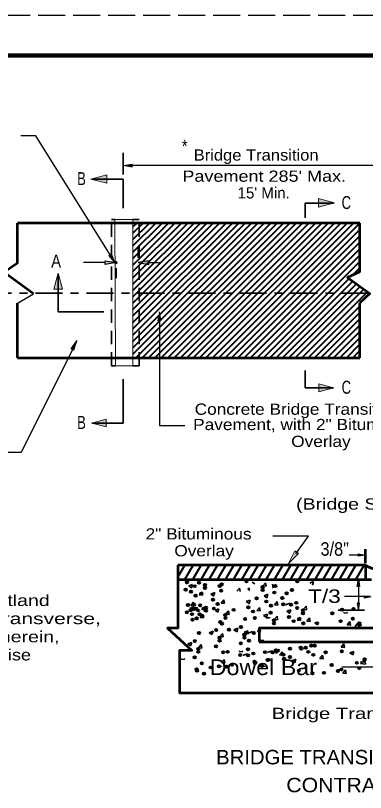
# Model space of a CAD drawing. Extents: x 36.4 to 71.7, y 0.5 to 22.5.
# Drawn here: x 50.93 to 55.29, y 12.78 to 22.48 of the extents above; entities that cross this region are included whole.
import ezdxf

# ---------------------------------------------------------------- set-up
doc = ezdxf.new("R2010")
doc.units = 0
doc.header["$LTSCALE"] = 0.056
doc.header["$PDMODE"] = 32
doc.header["$PDSIZE"] = 0.028
for name, pattern in [('LONG_DASH_SHORT_DASH', [9.9, 6, -1.2, 1.5, -1.2]), ('LONG_DASHED', [7.5, 6, -1.5]), ('MEDIUM_DASHED', [4.5, 3, -1.5])]:
    doc.linetypes.add(name, pattern=pattern)
for name, color, linetype, lineweight in [('1', 7, 'Continuous', 40), ('2', 7, 'MEDIUM_DASHED', 35), ('3', 7, 'Continuous', 13), ('5', 7, 'Continuous', 35), ('6', 7, 'Continuous', 13), ('7', 7, 'LONG_DASH_SHORT_DASH', 35)]:
    doc.layers.add(name, color=color, linetype=linetype, lineweight=lineweight)

msp = doc.modelspace()

# ---------------------------------------------------------------- hatches: boundary and pattern name
at = {"layer": '1'}
for points in [[(52.3805, 20.58408), (52.3805, 20.62158), (52.268, 20.60283), (52.268, 20.60283)], [(52.0445, 19.3695), (52.0445, 19.41475), (52.18058, 19.39217), (52.18058, 19.39217)], [(52.589, 19.3695), (52.589, 19.41475), (52.45283, 19.39217), (52.45283, 19.39217)], [(55.2145, 15.34717), (55.18525, 15.34717), (55.19983, 15.435), (55.19983, 15.435)], [(55.2145, 15.13917), (55.18525, 15.13917), (55.19983, 15.05125), (55.19983, 15.05125)]]:
    msp.add_hatch(color=256, dxfattribs=at).paths.add_polyline_path(points)
at = {"layer": '3'}
for points in [[(52.06208, 20.3825), (52.06208, 20.48933), (51.86283, 20.43583), (51.86283, 20.43583)], [(54.701, 20.19242), (54.701, 20.08558), (54.90033, 20.13908), (54.90033, 20.13908)], [(52.12417, 19.50175), (52.08858, 19.48083), (52.16908, 19.38467), (52.16908, 19.38467)], [(51.40508, 19.06058), (51.51192, 19.06058), (51.45842, 19.25992), (51.45842, 19.25992)], [(52.70158, 18.66583), (52.73908, 18.66583), (52.72025, 18.77833), (52.72025, 18.77833)], [(51.617, 18.31608), (51.65392, 18.29783), (51.69025, 18.41792), (51.69025, 18.41792)], [(54.70775, 17.87742), (54.70775, 17.78025), (54.88892, 17.82892), (54.88892, 17.82892)], [(52.05708, 17.34083), (52.05708, 17.438), (51.87592, 17.38933), (51.87592, 17.38933)], [(54.45417, 15.75925), (54.40658, 15.79342), (54.32783, 15.63367), (54.32783, 15.63367)], [(55.19842, 15.72658), (55.19842, 15.75592), (55.28633, 15.74125), (55.28633, 15.74125)], [(55.27283, 15.23242), (55.27283, 15.20317), (55.36075, 15.21775), (55.36075, 15.21775)]]:
    msp.add_hatch(color=256, dxfattribs=at).paths.add_polyline_path(points)

# ---------------------------------------------------------------- linework, layer by layer
at = {"layer": '1', "linetype": 'LONG_DASHED', "lineweight": 25}
msp.add_line((71.60142, 22.47742), (36.40142, 22.47742), dxfattribs=at)
at = {"layer": '1', "lineweight": 158}
msp.add_line((71.51808, 21.97742), (39.01808, 21.97742), dxfattribs=at)
at = {"layer": '1', "lineweight": 35}
for p, q in [((52.268, 20.49075), (52.268, 20.76483)), ((53.08492, 15.35508), (53.13417, 15.37408)), ((53.68542, 15.28792), (53.71925, 15.32842)), ((53.7275, 15.28442), (53.71925, 15.32842)), ((53.82008, 15.31725), (53.84817, 15.32808)), ((53.87617, 15.40358), (53.91125, 15.37992)), ((54.01025, 15.35525), (54.04417, 15.39567)), ((54.01025, 15.35525), (54.05225, 15.35167)), ((54.05225, 15.35167), (54.04417, 15.39567)), ((54.12808, 15.37617), (54.12867, 15.37692)), ((54.12808, 15.3335), (54.13675, 15.33275)), ((54.13675, 15.33275), (54.12867, 15.37683)), ((54.593, 15.39033), (54.64225, 15.40917)), ((54.62808, 15.36667), (54.64225, 15.40917)), ((53.21525, 15.24292), (53.24917, 15.28333)), ((53.21525, 15.24292), (53.25725, 15.23925)), ((53.25733, 15.23925), (53.24917, 15.28333)), ((53.35975, 15.25383), (53.409, 15.27283)), ((53.82008, 15.31725), (53.84817, 15.29833)), ((54.02383, 15.23183), (54.07308, 15.25083)), ((54.02383, 15.23183), (54.05883, 15.20825)), ((54.05883, 15.20825), (54.07308, 15.25083)), ((53.11017, 15.11092), (53.144, 15.15133)), ((53.15225, 15.10725), (53.144, 15.15133)), ((53.49008, 15.14167), (53.524, 15.18208)), ((53.49008, 15.14167), (53.53208, 15.138)), ((53.53217, 15.138), (53.524, 15.18208)), ((53.80175, 15.15925), (53.851, 15.17825)), ((54.15417, 15.11967), (54.18808, 15.16008)), ((54.19625, 15.116), (54.18808, 15.16008)), ((54.296, 15.12042), (54.34525, 15.13942)), ((54.33842, 15.11917), (54.34525, 15.13942)), ((53.09808, 15.0735), (53.14733, 15.0925)), ((53.11017, 15.11092), (53.15225, 15.10725)), ((53.13942, 15.04817), (53.18867, 15.06708)), ((53.13942, 15.04817), (53.1415, 15.04683)), ((53.18192, 15.04683), (53.18867, 15.06708)), ((53.413, 15.05092), (53.46225, 15.06975)), ((53.413, 15.05092), (53.44808, 15.02733)), ((53.44808, 15.02733), (53.46225, 15.06975)), ((53.54708, 15.00267), (53.58092, 15.04308)), ((53.589, 14.99908), (53.58092, 15.04308)), ((53.93208, 15.04708), (53.966, 15.0875)), ((53.93208, 15.04708), (53.97408, 15.04342)), ((53.97417, 15.04342), (53.966, 15.0875)), ((54.15417, 15.11967), (54.19617, 15.116)), ((54.296, 15.12042), (54.298, 15.11917)), ((54.3075, 15.03833), (54.35675, 15.05733)), ((54.51325, 15.06175), (54.54708, 15.10217)), ((54.51325, 15.06175), (54.55525, 15.05808)), ((54.55525, 15.05808), (54.54708, 15.10217)), ((55.2745, 15.05125), (54.94675, 15.05125)), ((53.22842, 14.96133), (53.26233, 15.00175)), ((53.22842, 14.96133), (53.27042, 14.95767)), ((53.2705, 14.95767), (53.26233, 15.00175)), ((53.54708, 15.00267), (53.589, 14.99908)), ((54.01775, 14.9845), (54.067, 15.00333)), ((54.01775, 14.9845), (54.05283, 14.96092)), ((54.05133, 14.95858), (54.058, 14.96658)), ((54.05133, 14.95858), (54.09333, 14.95483)), ((54.05283, 14.96092), (54.067, 15.00333)), ((54.09333, 14.95483), (54.09125, 14.96658)), ((54.15183, 14.93617), (54.18567, 14.97658)), ((54.19383, 14.9325), (54.18567, 14.97658)), ((54.43783, 14.92617), (54.47175, 14.96658)), ((54.47992, 14.9225), (54.47175, 14.96658)), ((54.55575, 14.91433), (54.58958, 14.95483)), ((54.59758, 14.91075), (54.58958, 14.95483)), ((55.0175, 15.01767), (55.02417, 15.02567)), ((55.0175, 15.01767), (55.05958, 15.01392)), ((55.05958, 15.01392), (55.0575, 15.02567)), ((54.15183, 14.93617), (54.19383, 14.9325)), ((54.43783, 14.92617), (54.47983, 14.9225)), ((54.55575, 14.91433), (54.59758, 14.91075)), ((54.65608, 14.89217), (54.66275, 14.90008)), ((54.65608, 14.89217), (54.69825, 14.88842)), ((54.69825, 14.88842), (54.69608, 14.90008)), ((55.05992, 14.87025), (55.09383, 14.91058)), ((55.1605, 14.848), (55.19433, 14.88842)), ((55.20242, 14.84433), (55.19433, 14.88842)), ((53.33933, 14.77042), (53.3885, 14.78942)), ((53.33933, 14.77042), (53.37425, 14.74692)), ((53.37425, 14.74692), (53.3885, 14.78942)), ((53.47333, 14.72217), (53.50725, 14.76267)), ((53.51525, 14.71858), (53.50725, 14.76267)), ((53.649, 14.80742), (53.69817, 14.82625)), ((53.649, 14.80742), (53.684, 14.78383)), ((53.684, 14.78383), (53.69817, 14.82625)), ((53.783, 14.75908), (53.817, 14.79958)), ((53.783, 14.75908), (53.825, 14.75542)), ((53.825, 14.75542), (53.817, 14.79958)), ((53.83275, 14.76783), (53.88192, 14.78683)), ((53.83275, 14.76783), (53.83475, 14.76658)), ((53.87517, 14.76658), (53.88192, 14.78683)), ((53.07375, 14.63025), (53.12292, 14.64925)), ((53.10875, 14.60683), (53.12292, 14.64925)), ((53.47333, 14.72217), (53.51525, 14.71858)), ((53.97758, 14.67808), (53.98433, 14.68608)), ((53.97758, 14.67808), (54.01967, 14.67433)), ((53.07375, 14.63025), (53.10875, 14.60683)), ((53.20775, 14.58208), (53.24158, 14.62258)), ((53.20775, 14.58208), (53.24975, 14.57842)), ((53.24975, 14.57842), (53.24158, 14.62258)), ((54.98625, 14.58992), (55.02008, 14.63017)), ((54.98625, 14.58992), (55.02833, 14.58617)), ((55.02833, 14.58617), (55.02025, 14.63017)), ((53.71208, 14.53792), (53.71875, 14.54592)), ((53.71208, 14.53792), (53.75417, 14.53417)), ((53.75417, 14.53417), (53.752, 14.54592)), ((53.759, 14.48733), (53.80825, 14.50633)), ((53.759, 14.48733), (53.761, 14.48608)), ((53.8015, 14.48608), (53.80825, 14.50633)), ((54.06875, 14.52433), (54.118, 14.54325)), ((54.06875, 14.52433), (54.07075, 14.52292)), ((54.11117, 14.52292), (54.118, 14.54325)), ((54.21642, 14.49375), (54.25025, 14.53417)), ((54.21642, 14.49375), (54.25833, 14.49017)), ((54.25833, 14.49017), (54.25025, 14.53417)), ((54.72075, 14.44975), (54.75458, 14.49)), ((54.76275, 14.446), (54.75467, 14.49)), ((55.09475, 14.51767), (55.144, 14.5365)), ((55.09475, 14.51767), (55.12967, 14.49417)), ((55.12967, 14.49417), (55.144, 14.5365)), ((52.98933, 14.442), (52.996, 14.45008)), ((52.98933, 14.442), (53.03142, 14.43825)), ((53.03142, 14.43825), (53.02925, 14.45008)), ((53.49375, 14.39775), (53.52758, 14.43825)), ((53.49375, 14.39775), (53.53575, 14.39425)), ((53.53575, 14.39425), (53.52758, 14.43825)), ((53.53592, 14.34592), (53.54275, 14.36617)), ((54.37208, 14.42167), (54.42125, 14.44067)), ((54.72075, 14.44975), (54.76275, 14.446)), ((55.22508, 14.40558), (55.267, 14.40192)), ((55.22625, 14.386), (55.281, 14.44308)), ((55.22625, 14.386), (55.28867, 14.37625)), ((55.26708, 14.40192), (55.25892, 14.446)), ((55.28883, 14.37625), (55.281, 14.44308)), ((53.4935, 14.34717), (53.4955, 14.34592)), ((53.998, 14.35375), (54.04008, 14.35)), ((54.5445, 14.30592), (54.53625, 14.35)), ((55.00667, 14.26558), (55.04058, 14.30583)), ((55.00667, 14.26558), (55.04867, 14.26183)), ((55.04867, 14.26183), (55.04058, 14.30583))]:
    msp.add_line(p, q, dxfattribs=at)
at = {"layer": '1', "lineweight": 25}
for p, q in [((55.47983, 20.60283), (52.3805, 20.60283)), ((52.45283, 19.45242), (52.45283, 19.58825)), ((51.90833, 19.39217), (51.77225, 19.39217)), ((52.0445, 19.39217), (51.90833, 19.39217)), ((52.18058, 19.32408), (52.18058, 19.19617)), ((52.589, 19.39217), (52.72508, 19.39217)), ((50.95067, 18.88392), (51.14917, 19.00392)), ((55.19983, 15.34717), (55.19983, 15.13917))]:
    msp.add_line(p, q, dxfattribs=at)
at = {"layer": '1', "lineweight": 53}
for p, q in [((55.2185, 19.88608), (50.95067, 19.88608)), ((55.2185, 19.27667), (55.2185, 19.88608)), ((50.95067, 18.20475), (50.95067, 18.88392)), ((55.2185, 18.20475), (55.2185, 18.88908)), ((50.95067, 18.20475), (55.2185, 18.20475)), ((55.28392, 15.81458), (55.28392, 15.63742)), ((55.28792, 15.61458), (52.95075, 15.61458)), ((55.28792, 15.61458), (55.28792, 15.44425)), ((52.95075, 15.435), (55.36242, 15.435))]:
    msp.add_line(p, q, dxfattribs=at)
at = {"layer": '1', "lineweight": 13}
msp.add_line((52.38967, 19.88608), (52.38967, 18.20475), dxfattribs=at)
at = {"layer": '1'}
for p, q in [((52.38967, 18.24867), (54.02708, 19.88608)), ((52.38967, 18.32825), (53.9475, 19.88608)), ((52.38967, 18.40783), (53.868, 19.88608)), ((52.38967, 18.48733), (53.78842, 19.88608)), ((52.38967, 18.56692), (53.70892, 19.88608)), ((52.38967, 18.6465), (53.62942, 19.88608)), ((52.38967, 18.726), (53.54983, 19.88608)), ((52.38967, 18.80558), (53.47025, 19.88608)), ((52.38967, 18.88517), (53.39075, 19.88608)), ((52.38967, 18.96467), (53.31117, 19.88608)), ((52.38967, 19.04425), (53.23158, 19.88608)), ((52.38967, 19.12383), (53.15208, 19.88608)), ((52.38967, 19.20333), (53.0725, 19.88608)), ((52.38967, 19.28283), (52.99292, 19.88608)), ((52.38967, 19.36242), (52.91342, 19.88608)), ((52.38967, 19.44192), (52.83383, 19.88608)), ((52.38967, 19.5215), (52.75425, 19.88608)), ((52.38967, 19.60108), (52.67475, 19.88608)), ((52.38967, 19.68058), (52.59517, 19.88608)), ((52.38967, 19.76017), (52.51567, 19.88608)), ((52.38967, 19.83975), (52.43617, 19.88608)), ((52.42533, 18.20475), (54.10667, 19.88608)), ((52.50492, 18.20475), (54.18617, 19.88608)), ((52.58442, 18.20475), (54.26575, 19.88608)), ((52.664, 18.20475), (54.34533, 19.88608)), ((52.74358, 18.20475), (54.42483, 19.88608)), ((52.82308, 18.20475), (54.50442, 19.88608)), ((52.90267, 18.20475), (54.584, 19.88608)), ((52.98217, 18.20475), (54.6635, 19.88608)), ((53.06167, 18.20475), (54.74308, 19.88608)), ((53.14125, 18.20475), (54.82267, 19.88608)), ((53.22075, 18.20475), (54.90217, 19.88608)), ((53.30033, 18.20475), (54.98167, 19.88608)), ((53.37992, 18.20475), (55.06117, 19.88608)), ((53.45942, 18.20475), (55.14075, 19.88608)), ((53.539, 18.20475), (55.2185, 19.88425)), ((53.61858, 18.20475), (55.2185, 19.80467)), ((53.69808, 18.20475), (55.2185, 19.72517)), ((53.77767, 18.20475), (55.2185, 19.64558)), ((53.85725, 18.20475), (55.2185, 19.566)), ((53.93675, 18.20475), (55.2185, 19.4865)), ((54.01633, 18.20475), (55.2185, 19.40692)), ((55.123, 19.23192), (55.2185, 19.32733)), ((54.09592, 18.20475), (55.08342, 19.19233)), ((54.17542, 18.20475), (55.12967, 19.159)), ((54.25492, 18.20475), (55.17592, 19.12567)), ((54.3345, 18.20475), (55.22217, 19.09233)), ((54.414, 18.20475), (55.26833, 19.05908)), ((54.49358, 18.20475), (55.31467, 19.02575)), ((54.57317, 18.20475), (55.2185, 18.85008)), ((54.65267, 18.20475), (55.2185, 18.77058)), ((54.73225, 18.20475), (55.2185, 18.691)), ((54.81183, 18.20475), (55.2185, 18.61142)), ((54.89133, 18.20475), (55.2185, 18.53192)), ((54.97092, 18.20475), (55.2185, 18.45233)), ((55.0505, 18.20475), (55.2185, 18.37275)), ((55.13, 18.20475), (55.2185, 18.29325)), ((55.20958, 18.20475), (55.2185, 18.21367)), ((52.95075, 15.46258), (53.0385, 15.61458)), ((53.03633, 15.435), (53.13992, 15.61458)), ((53.13783, 15.435), (53.24142, 15.61458)), ((53.23925, 15.435), (53.34283, 15.61458)), ((53.34083, 15.435), (53.44442, 15.61458)), ((53.44225, 15.435), (53.54583, 15.61458)), ((53.54375, 15.435), (53.64733, 15.61458)), ((53.64525, 15.435), (53.74883, 15.61458)), ((53.74675, 15.435), (53.85033, 15.61458)), ((53.84817, 15.435), (53.95175, 15.61458)), ((53.94975, 15.435), (54.05333, 15.61458)), ((54.05117, 15.435), (54.15475, 15.61458)), ((54.15267, 15.435), (54.25625, 15.61458)), ((54.25408, 15.435), (54.35792, 15.61458)), ((54.35567, 15.435), (54.45933, 15.61458)), ((54.45708, 15.435), (54.56083, 15.61458)), ((54.55858, 15.435), (54.66233, 15.61458)), ((54.66008, 15.435), (54.76383, 15.61458)), ((54.76158, 15.435), (54.86525, 15.61458)), ((54.863, 15.435), (54.96683, 15.61458)), ((54.96458, 15.435), (55.06825, 15.61458)), ((55.066, 15.435), (55.16975, 15.61458)), ((55.1675, 15.435), (55.27125, 15.61458))]:
    msp.add_line(p, q, dxfattribs=at)
at = {"layer": '1', "lineweight": 13}
for points in [[(52.3805, 20.58408), (52.3805, 20.62158), (52.268, 20.60283), (52.268, 20.60283)], [(52.17092, 18.10483), (52.387, 18.10483), (52.387, 19.93192), (52.162, 19.93192)]]:
    msp.add_lwpolyline(points, close=True, dxfattribs=at)
at = {"layer": '1', "lineweight": 53}
for points in [[(51.14917, 19.00392), (50.7805, 19.27175), (50.95067, 19.38883), (50.95067, 19.88608)], [(55.2185, 19.27667), (55.06567, 19.20508), (55.3415, 19.00633), (55.2185, 18.88908)], [(52.95075, 15.61458), (52.95075, 14.829), (52.82233, 14.829), (53.12183, 14.54867), (52.972, 14.54867), (52.972, 14.02125), (57.945, 14.02125), (57.945, 14.571), (58.12675, 14.571), (57.76308, 14.84025), (57.9235, 14.84025)]]:
    msp.add_lwpolyline(points, dxfattribs=at)
at = {"layer": '1', "lineweight": 25}
for points in [[(52.0445, 19.3695), (52.0445, 19.41475), (52.18058, 19.39217), (52.18058, 19.39217)], [(52.589, 19.3695), (52.589, 19.41475), (52.45283, 19.39217), (52.45283, 19.39217)], [(55.2145, 15.34717), (55.18525, 15.34717), (55.19983, 15.435), (55.19983, 15.435)], [(55.2145, 15.13917), (55.18525, 15.13917), (55.19983, 15.05125), (55.19983, 15.05125)]]:
    msp.add_lwpolyline(points, close=True, dxfattribs=at)
at = {"layer": '1', "lineweight": 35}
for points in [[(53.08492, 15.35508), (53.11992, 15.3315), (53.13417, 15.37408)], [(53.35975, 15.25383), (53.39475, 15.23025), (53.409, 15.27283)], [(53.80175, 15.15925), (53.83675, 15.13567), (53.851, 15.17825)], [(53.09808, 15.0735), (53.13308, 15.04992), (53.14733, 15.0925)], [(54.3075, 15.03833), (54.3425, 15.01475), (54.35675, 15.05733)], [(55.05992, 14.87025), (55.102, 14.8665), (55.09392, 14.91058)], [(54.37208, 14.42167), (54.40692, 14.39817), (54.42125, 14.44067)]]:
    msp.add_lwpolyline(points, dxfattribs=at)
at = {"layer": '1', "lineweight": 53}
msp.add_lwpolyline([(53.96333, 14.65867), (56.92392, 14.65867), (56.92392, 14.82925), (53.96333, 14.82925)], close=True, dxfattribs=at)
at = {"layer": '1', "lineweight": 60}
msp.add_arc((55.44258, 15.83602), 0.2701, 235.06709, 304.93291, dxfattribs=at)
at = {"layer": '1'}
for p in [(53.80575, 15.41125), (54.43808, 15.41267), (53.06292, 15.3985), (53.16167, 15.3525), (53.2145, 15.39583), (53.2865, 15.3665), (53.28767, 15.32842), (53.47175, 15.35358), (53.496, 15.37442), (54.00625, 15.34325), (54.16592, 15.35425), (53.04833, 15.3085), (53.11233, 15.28367), (53.171, 15.23208), (53.2425, 15.25858), (53.48933, 15.29458), (54.00725, 15.30525), (54.15342, 15.27258), (54.30592, 15.26133), (54.37217, 15.30575), (53.38717, 15.18242), (53.44583, 15.13083), (53.93133, 15.2), (54.05125, 15.16042), (54.25092, 15.20483), (54.26358, 15.12417), (54.35967, 15.12067), (54.4265, 15.14442), (53.0615, 15.02692), (53.07608, 15.11692), (53.107, 15.05192), (53.12958, 15.06625), (53.15008, 15.11967), (53.17483, 15.07092), (53.20308, 15.04833), (53.22767, 15.11425), (53.27, 15.07217), (53.29967, 15.08492), (53.30083, 15.04683), (53.39808, 15.07317), (53.64542, 15.05625), (53.82917, 15.08783), (53.88783, 15.03625), (54.10992, 15.10883), (54.43708, 15.07908), (54.50908, 15.04975), (54.99633, 15.05917), (55.13892, 15.06642), (53.1255, 15.00208), (53.13258, 14.93308), (53.18417, 14.9505), (53.22183, 15), (53.25567, 14.977), (53.54292, 14.99067), (53.544, 14.95258), (53.78858, 14.94317), (53.90892, 14.95317), (54.1055, 15.02008), (54.33492, 14.96692), (54.46508, 14.94183), (54.51025, 15.01167), (54.87508, 15.01225), (55.13067, 14.94667), (53.47883, 14.90617), (53.49883, 14.88283), (53.73683, 14.84308), (54.14775, 14.92417), (54.14883, 14.88617), (54.39358, 14.91533), (54.51375, 14.88667), (54.68667, 14.88825), (54.97775, 14.91517), (55.21067, 14.889), (55.21775, 14.87208), (53.21333, 14.766), (53.42708, 14.80608), (53.58792, 14.80783), (53.779, 14.74717), (53.80025, 14.77158), (53.89633, 14.76808), (53.96333, 14.79183), (53.1615, 14.66592), (53.46925, 14.71033), (53.47025, 14.67217), (53.73492, 14.63917), (53.78, 14.709), (53.83525, 14.67283), (53.20367, 14.57008), (53.42517, 14.60233), (53.824, 14.56417), (54.17067, 14.54958), (54.19925, 14.54833), (54.34675, 14.57283), (54.48042, 14.58658), (54.48758, 14.5695), (54.54308, 14.58525), (54.613, 14.60775), (54.6565, 14.60967), (54.99375, 14.53967), (53.15958, 14.46217), (53.20475, 14.532), (53.51425, 14.52733), (53.56967, 14.53258), (53.72658, 14.49108), (53.82267, 14.48758), (53.88958, 14.51142), (54.03633, 14.52808), (54.13242, 14.5245), (54.17792, 14.53258), (54.26492, 14.49558), (54.271, 14.44367), (54.2775, 14.44517), (54.34742, 14.46767), (54.57467, 14.53258), (54.6385, 14.49467), (54.7915, 14.52617), (53.24867, 14.38717), (53.461, 14.35092), (53.55475, 14.34925), (53.55708, 14.34742), (53.624, 14.37133), (53.62475, 14.37175), (53.90517, 14.40942), (53.91233, 14.39242), (53.91583, 14.39867), (53.99942, 14.35542), (54.06875, 14.43017), (54.08117, 14.43267), (54.86808, 14.36908), (55.18075, 14.39467), (55.27825, 14.43942), (53.1825, 14.31342), (53.18958, 14.29642), (53.27667, 14.25942), (53.3585, 14.33667), (54.458, 14.29867), (54.62758, 14.26233), (54.77025, 14.2695), (54.94625, 14.29267), (54.98867, 14.31183), (55.2125, 14.32783)]:
    msp.add_point(p, dxfattribs=at)
at = {"layer": '2'}
for p, q in [((52.162, 19.93192), (52.1205, 19.93192)), ((52.387, 19.93192), (52.468, 19.93192))]:
    msp.add_line(p, q, dxfattribs=at)
for points in [[(52.171, 18.10483), (52.1205, 18.10483), (52.1205, 19.93192)], [(52.387, 18.10483), (52.468, 18.10483), (52.468, 19.93192)]]:
    msp.add_lwpolyline(points, dxfattribs=at)
at = {"layer": '3', "lineweight": 25}
for p, q in [((54.57858, 15.97758), (54.13342, 15.97758)), ((54.41967, 15.7565), (54.57858, 15.97758)), ((55.26125, 15.74008), (55.08592, 15.74008)), ((55.349, 15.22217), (55.02717, 15.22217))]:
    msp.add_line(p, q, dxfattribs=at)
for points in [[(52.10767, 19.49058), (51.17875, 20.97692), (50.9935, 20.97692)], [(52.72033, 18.66583), (52.72033, 17.3595), (53.03733, 17.3595)], [(51.68808, 18.40858), (50.99792, 17.0205), (50.60792, 17.0205)], [(55.59508, 14.50492), (55.50375, 14.33992), (54.99492, 14.33992)]]:
    msp.add_lwpolyline(points, dxfattribs=at)
at = {"layer": '3'}
for points in [[(52.06208, 20.3825), (52.06208, 20.48933), (51.86283, 20.43583), (51.86283, 20.43583)], [(54.701, 20.19242), (54.701, 20.08558), (54.90033, 20.13908), (54.90033, 20.13908)], [(52.12417, 19.50175), (52.08858, 19.48083), (52.16908, 19.38467), (52.16908, 19.38467)], [(51.40508, 19.06058), (51.51192, 19.06058), (51.45842, 19.25992), (51.45842, 19.25992)], [(52.70158, 18.66583), (52.73908, 18.66583), (52.72025, 18.77833), (52.72025, 18.77833)], [(51.617, 18.31608), (51.65392, 18.29783), (51.69025, 18.41792), (51.69025, 18.41792)], [(54.70775, 17.87742), (54.70775, 17.78025), (54.88892, 17.82892), (54.88892, 17.82892)], [(52.05708, 17.34083), (52.05708, 17.438), (51.87592, 17.38933), (51.87592, 17.38933)], [(54.45417, 15.75925), (54.40658, 15.79342), (54.32783, 15.63367), (54.32783, 15.63367)], [(55.19842, 15.72658), (55.19842, 15.75592), (55.28633, 15.74125), (55.28633, 15.74125)], [(55.27283, 15.23242), (55.27283, 15.20317), (55.36075, 15.21775), (55.36075, 15.21775)]]:
    msp.add_lwpolyline(points, close=True, dxfattribs=at)
at = {"layer": '5'}
for p, q in [((51.87592, 20.4345), (52.268, 20.4345)), ((52.268, 20.07333), (52.268, 20.4345)), ((51.45842, 19.24742), (51.45842, 18.7795)), ((52.02542, 18.7795), (51.45842, 18.7795)), ((54.53758, 17.82892), (54.53758, 18.046)), ((52.268, 17.93525), (52.268, 17.38933)), ((54.88892, 17.82892), (54.53758, 17.82892)), ((51.87592, 17.38933), (52.268, 17.38933))]:
    msp.add_line(p, q, dxfattribs=at)
msp.add_lwpolyline([(54.88892, 20.1355), (54.53758, 20.1355), (54.53758, 19.95083)], dxfattribs=at)
at = {"layer": '6'}
for p, q in [((52.268, 20.60283), (52.26808, 20.60283)), ((52.268, 20.4345), (52.26808, 20.4345))]:
    msp.add_line(p, q, dxfattribs=at)
at = {"layer": '6', "lineweight": 25}
for p, q in [((52.45283, 19.38442), (52.45292, 19.38442)), ((55.19983, 15.05125), (55.2, 15.05125))]:
    msp.add_line(p, q, dxfattribs=at)
at = {"layer": '6'}
msp.add_point((52.18058, 19.39217), dxfattribs=at)
at = {"layer": '7'}
msp.add_line((50.53942, 19.01133), (60.50117, 19.01133), dxfattribs=at)

# ---------------------------------------------------------------- texts
at = {"layer": '1', "width": 1.1}
msp.add_text('Bridge Transition', height=0.14, dxfattribs=at).set_placement((53.14717, 20.66583))
at = {"layer": '3'}
for s, height, width, p in [('*', 0.162, 0.85, (52.99925, 20.76442)), ("Pavement 285' Max.", 0.14, 1.2, (53.006, 20.40183)), ('Concrete Bridge Transition', 0.14, 1.15, (53.15883, 17.49225)), ('Pavement, with 2" Bituminous', 0.14, 1.15, (53.13992, 17.301)), ('Overlay', 0.14, 1.15, (54.36258, 17.09067)), ('(Bridge Skew Greater Than 15°)', 0.14, 1.3, (54.42342, 16.30808)), ('2" Bituminous ', 0.14, 1.15, (52.54758, 15.935)), (' Overlay', 0.14, 1.15, (52.84567, 15.7245)), ('3/8"', 0.1687, 0.9, (54.72792, 15.73225)), ('Bridge Transition Pavement shall be Portland', 0.14, 1.3, (46.46817, 15.10467)), ('T/3', 0.1687, 1.25, (54.57275, 15.14283)), ('Cement Concrete Pavement having transverse,', 0.14, 1.4, (46.46817, 14.878)), ('unsealed contraction joints, as detailed herein,', 0.14, 1.3, (46.46817, 14.65133)), ("at a maximum spacing of 15', unless otherwise", 0.14, 1.2, (46.46817, 14.42467)), ('Dowel Bar', 0.1969, 1.1, (53.34725, 14.24158)), ('Bridge Transition Pavement', 0.14, 1.35, (54.11892, 13.69375)), ('BRIDGE TRANSITION PAVEMENT', 0.18, 1.05, (53.42692, 13.12717)), ('CONTRACTION JOINTS', 0.18, 1.1, (54.30158, 12.77875))]:
    msp.add_text(s, height=height, dxfattribs=dict(at, width=width)).set_placement(p)
msp.add_text("15' Min.", height=0.14, dxfattribs=at).set_placement((53.6945, 20.19308))
at = {"layer": '5'}
for s, width, p in [('B', 0.75, (51.69417, 20.36025)), ('C', 0.75, (54.9915, 20.06133)), ('A', 0.85, (51.37058, 19.33033)), ('C', 0.75, (54.9915, 17.75475)), ('B', 0.75, (51.69417, 17.31517))]:
    msp.add_text(s, height=0.162, dxfattribs=dict(at, width=width)).set_placement(p)

doc.saveas('drawing.dxf')
